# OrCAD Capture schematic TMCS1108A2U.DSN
size A; title: TMCS1108 3% Functional Isolation Hall-Effect Current Sensor; rev: A
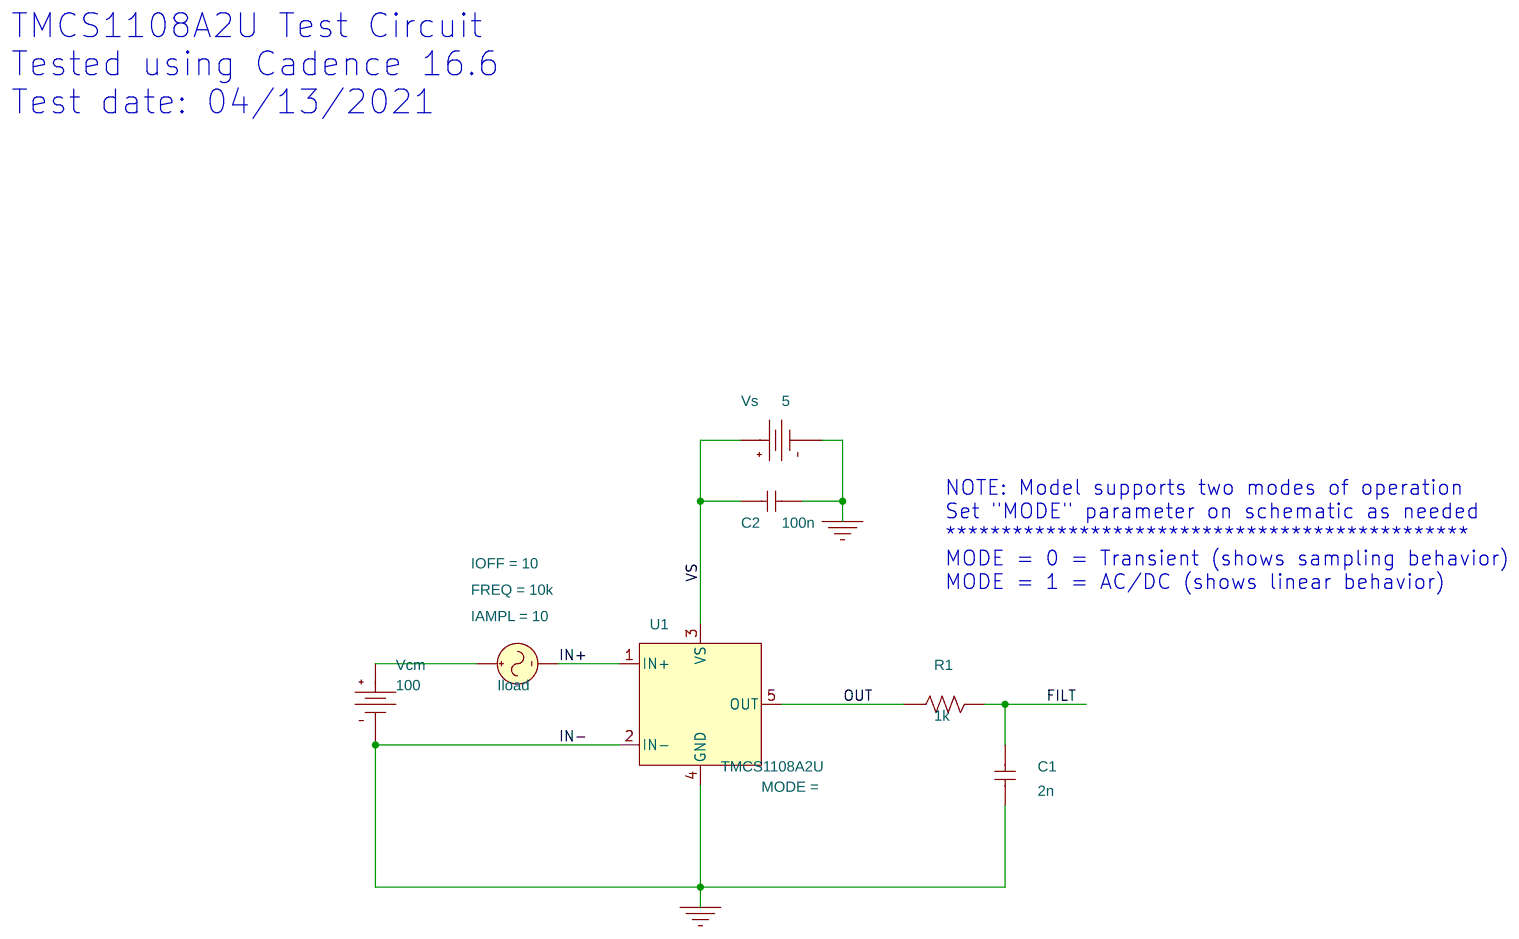
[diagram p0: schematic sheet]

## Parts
C1  2n  [RAD/CK05]
C2  100n  [RAD/CK05]
Iload  ISIN
R1  1k  [AX/RC05]
U1  TMCS1108A2U
Vcm  VDC
Vs  VDC

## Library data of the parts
C1 C2 = C
Iload = ISIN: FREQ: 10k; IAMPL: 10; IOFF: 10
R1 = R
U1 = TMCS1108A2U
Vcm = VDC: DC: 100
Vs = VDC: DC: 5

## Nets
0: C1.1 C2.1 U1.2(IN-) U1.4(GND) Vcm.1(-) Vs.1(-)
FILT: C1.2 R1.2
IN+: Iload.2(-) U1.1(IN+)
OUT: R1.1 U1.5(OUT)
VS: C2.2 U1.3(VS) Vs.0(+)
N1379374: Iload.1(+) Vcm.0(+)

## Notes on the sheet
- TMCS1108A2U Test Circuit
  Tested using Cadence 16.6
  Test date: 04/13/2021
- NOTE: Model supports two modes of operation
  Set "MODE" parameter on schematic as needed
  ***********************************************
  MODE = 0 = Transient (shows sampling behavior)
  MODE = 1 = AC/DC (shows linear behavior)
